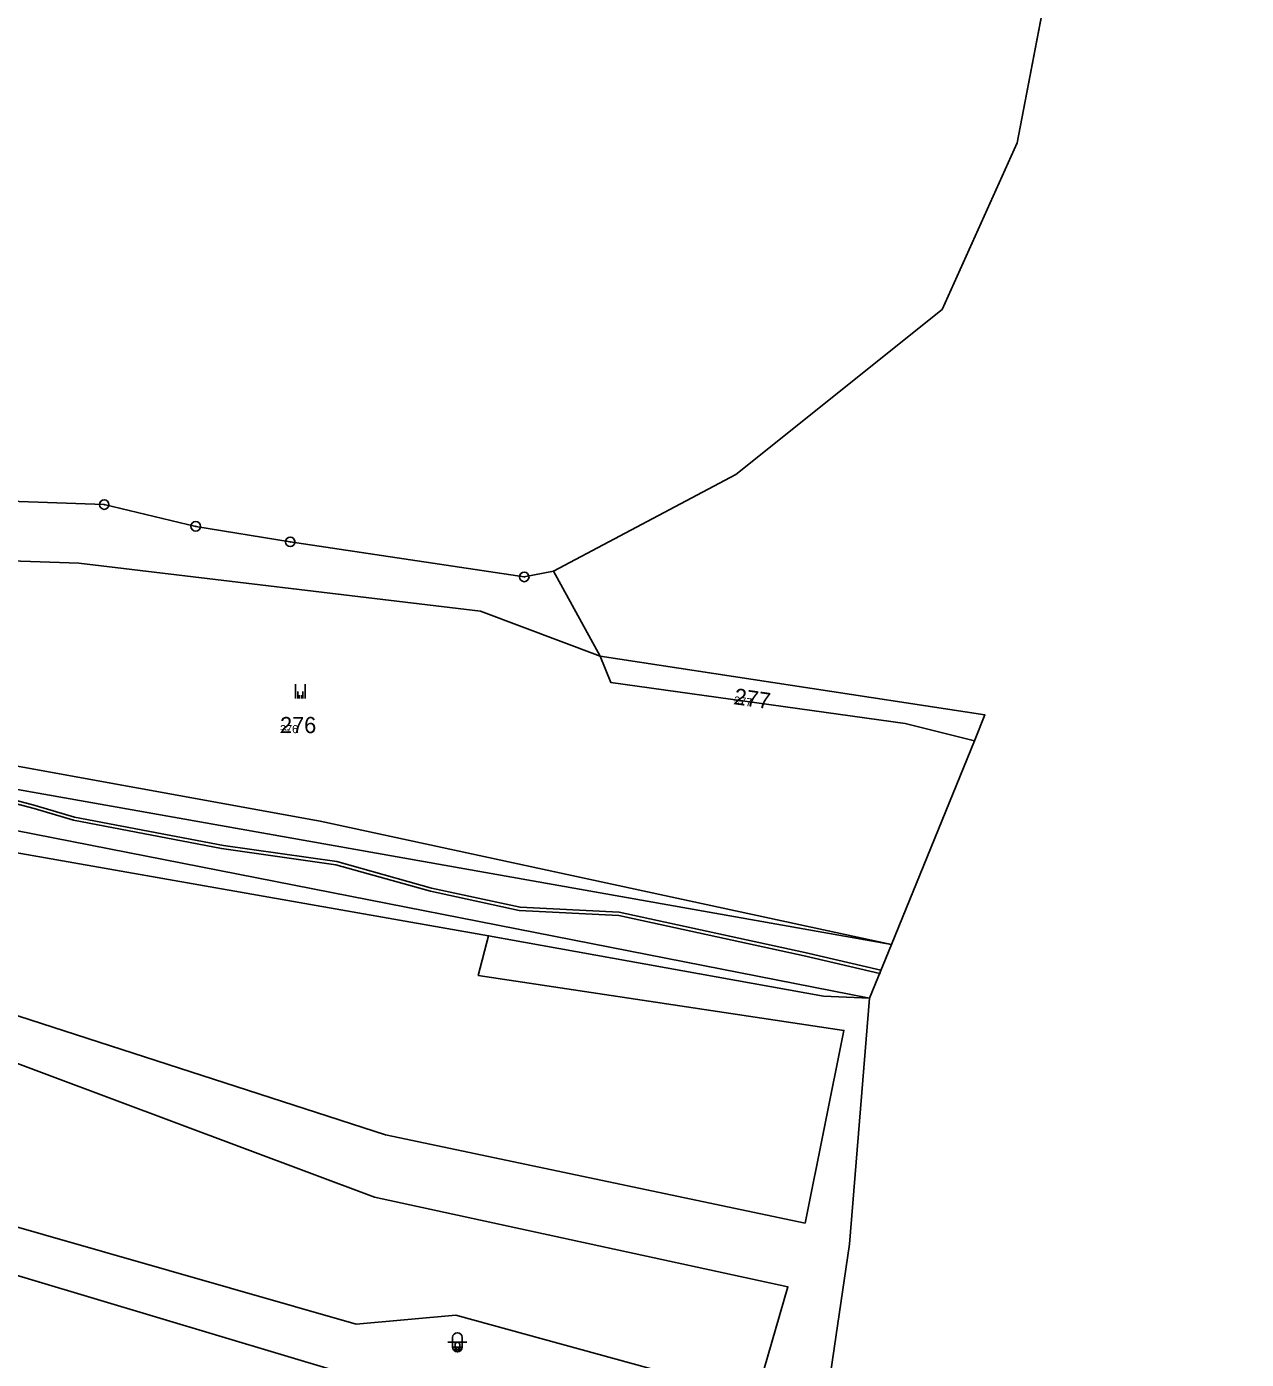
# Model space of a CAD drawing. Extents: x -759873 to -758487, y -975024 to -973516.
# Drawn here: x -758688 to -758560.1, y -974535.9 to -974396.2 of the extents above; entities that cross this region are included whole.
import ezdxf

# ---------------------------------------------------------------- set-up
doc = ezdxf.new("R2010")
doc.units = 0
for name, color, linetype in [('KAT_01_hranice KU', 7, 'Continuous'), ('KAT_02_hranice parcel', 7, 'Continuous'), ('KAT_03_1000_čísla parcelní', 7, 'Continuous'), ('KAT_03_250_čísla parcelní', 7, 'Continuous'), ('KAT_03_500_čísla parcelní', 7, 'Continuous'), ('KAT_04_vnitřní kresba', 7, 'Continuous'), ('KAT_05_1000_značky kultur', 7, 'Continuous'), ('KAT_05_250_značky kultur', 7, 'Continuous'), ('KAT_05_500_značky kultur', 7, 'Continuous'), ('KAT_10_věcná břemena', 7, 'Continuous'), ('KAT_11_značky bodu BP', 7, 'Continuous'), ('KAT_14_plocha_pozemek', 7, 'Continuous')]:
    doc.layers.add(name, color=color, linetype=linetype)

msp = doc.modelspace()

# ---------------------------------------------------------------- linework, layer by layer
at = {"layer": 'KAT_01_hranice KU'}
msp.add_lwpolyline([(-758607.97, -974566.39), (-758601.73, -974523.85), (-758599.61, -974498.06), (-758597.31, -974492.42), (-758588.63, -974471.08), (-758587.52, -974468.35), (-758627.86, -974462.19), (-758632.75, -974453.28), (-758613.64, -974443.17), (-758592.01, -974425.87), (-758584.15, -974408.39), (-758577.48, -974373.63), (-758560.12, -974371.49), (-758566.72, -974342.84), (-758577.45, -974305.32), (-758579.96, -974284.59)], dxfattribs=at)
at = {"layer": 'KAT_02_hranice parcel'}
for p, q in [((-758584.15, -974408.39), (-758577.48, -974373.63)), ((-758592.01, -974425.87), (-758584.15, -974408.39)), ((-758613.64, -974443.17), (-758592.01, -974425.87)), ((-758632.75, -974453.28), (-758613.64, -974443.17)), ((-758627.86, -974462.19), (-758632.75, -974453.28)), ((-758587.52, -974468.35), (-758627.86, -974462.19)), ((-758588.63, -974471.08), (-758587.52, -974468.35)), ((-758597.31, -974492.42), (-758588.63, -974471.08)), ((-758599.61, -974498.06), (-758597.31, -974492.42))]:
    msp.add_line(p, q, dxfattribs=at)
for points in [[(-758632.75, -974453.28), (-758635.81, -974453.89), (-758660.34, -974450.22), (-758670.25, -974448.59), (-758679.84, -974446.31), (-758718.48, -974444.93), (-758753.38, -974423.47), (-758781.23, -974399.3), (-758797.06, -974363.45), (-758834.16, -974346.1), (-758865.99, -974333.25), (-758907.24, -974318.32), (-758952.22, -974315.62)], [(-758718.12, -974451.24), (-758682.5, -974452.45), (-758640.39, -974457.49), (-758627.86, -974462.19)], [(-758588.63, -974471.08), (-758595.89, -974469.25), (-758626.75, -974464.95), (-758627.86, -974462.19)], [(-758597.31, -974492.42), (-758602.67, -974491.26), (-758657.21, -974479.48), (-758695.33, -974472.59), (-758723.99, -974463.52)], [(-758727.47, -974470.86), (-758699.13, -974481.04), (-758639.55, -974491.51)], [(-758639.55, -974491.51), (-758640.63, -974495.69), (-758602.31, -974501.43), (-758606.38, -974521.63), (-758650.34, -974512.39), (-758704.47, -974494.86), (-758706.61, -974498.3), (-758651.5, -974518.9), (-758608.18, -974528.3), (-758611.55, -974539.9), (-758642.99, -974531.28), (-758653.42, -974532.21), (-758712.61, -974515.26), (-758713.61, -974519.76), (-758648.23, -974539.32), (-758612.86, -974545.85), (-758615.06, -974562.12), (-758700.21, -974537.79), (-758703.41, -974545.99), (-758657.92, -974561.88), (-758653.86, -974564.39)], [(-758599.61, -974498.06), (-758604.44, -974497.84), (-758639.55, -974491.51)], [(-758607.97, -974566.39), (-758601.73, -974523.85), (-758599.61, -974498.06)]]:
    msp.add_lwpolyline(points, dxfattribs=at)
at = {"layer": 'KAT_04_vnitřní kresba'}
for p, q in [((-758696.4, -974474.85), (-758597.31, -974492.42)), ((-758697.6, -974478.8), (-758599.61, -974498.06))]:
    msp.add_line(p, q, dxfattribs=at)
at = {"layer": 'KAT_05_1000_značky kultur'}
for p, q in [((-758659.78, -974466.64), (-758659.78, -974465.14)), ((-758658.78, -974466.64), (-758658.78, -974465.14)), ((-758643.82, -974534.12), (-758641.82, -974534.12)), ((-758643.32, -974533.62), (-758643.32, -974534.62)), ((-758642.32, -974534.62), (-758642.32, -974533.62))]:
    msp.add_line(p, q, dxfattribs=at)
for centre, start, end in [((-758642.82, -974533.62), 0, 180), ((-758642.82, -974534.62), 180, 359.9879)]:
    msp.add_arc(centre, 0.5, start, end, dxfattribs=at)
at = {"layer": 'KAT_05_250_značky kultur'}
for p, q in [((-758659.4, -974466.64), (-758659.4, -974466.27)), ((-758659.15, -974466.64), (-758659.15, -974466.27)), ((-758643.07, -974534.87), (-758642.57, -974534.87)), ((-758642.95, -974534.75), (-758642.95, -974535)), ((-758642.69, -974535), (-758642.69, -974534.75))]:
    msp.add_line(p, q, dxfattribs=at)
for centre, start, end in [((-758642.82, -974534.75), 0, 180), ((-758642.82, -974535), 180, 359.9879)]:
    msp.add_arc(centre, 0.125, start, end, dxfattribs=at)
at = {"layer": 'KAT_05_500_značky kultur'}
for p, q in [((-758659.53, -974466.64), (-758659.53, -974465.89)), ((-758659.03, -974466.64), (-758659.03, -974465.89)), ((-758643.07, -974534.37), (-758643.07, -974534.87)), ((-758642.57, -974534.87), (-758642.57, -974534.37)), ((-758643.32, -974534.62), (-758642.32, -974534.62))]:
    msp.add_line(p, q, dxfattribs=at)
for centre, start, end in [((-758642.82, -974534.37), 0, 180), ((-758642.82, -974534.87), 180, 359.9879)]:
    msp.add_arc(centre, 0.25, start, end, dxfattribs=at)
at = {"layer": 'KAT_10_věcná břemena'}
msp.add_lwpolyline([(-758698.63, -974475.15), (-758687.19, -974478.18), (-758683.05, -974479.39), (-758667.55, -974482.35), (-758655.56, -974484.06), (-758645.65, -974486.85), (-758636.34, -974488.86), (-758625.91, -974489.38), (-758606.48, -974493.61), (-758598.55, -974495.46), (-758598.44, -974495.13), (-758606.4, -974493.27), (-758625.87, -974489.04), (-758636.24, -974488.52), (-758645.55, -974486.51), (-758655.46, -974483.72), (-758667.33, -974482.03), (-758682.95, -974479.06), (-758687.09, -974477.84), (-758698.47, -974474.83)], dxfattribs=at)
at = {"layer": 'KAT_11_značky bodu BP'}
for centre, radius in [((-758679.84, -974446.31), 0.5), ((-758679.84, -974446.31), 0.0303), ((-758670.25, -974448.59), 0.5), ((-758670.25, -974448.59), 0.0303), ((-758660.34, -974450.22), 0.5), ((-758660.34, -974450.22), 0.0303), ((-758635.81, -974453.89), 0.5), ((-758635.81, -974453.89), 0.0303)]:
    msp.add_circle(centre, radius, dxfattribs=at)
at = {"layer": 'KAT_14_plocha_pozemek'}
for points in [[(-758834.16, -974346.1), (-758797.06, -974363.45), (-758781.23, -974399.3), (-758753.38, -974423.47), (-758718.48, -974444.93), (-758679.84, -974446.31), (-758670.25, -974448.59), (-758660.34, -974450.22), (-758635.81, -974453.89), (-758632.75, -974453.28), (-758613.64, -974443.17), (-758592.01, -974425.87), (-758584.15, -974408.39), (-758577.48, -974373.63), (-758560.12, -974371.49), (-758566.72, -974342.84), (-758577.45, -974305.32), (-758579.96, -974284.59)], [(-758822.78, -974356.75), (-758805.35, -974369.54), (-758794.34, -974384.71), (-758781.96, -974405.06), (-758777.78, -974408.08), (-758761.72, -974419.22), (-758750.8, -974427.84), (-758717.38, -974449.33), (-758718.12, -974451.24), (-758682.5, -974452.45), (-758640.39, -974457.49), (-758627.86, -974462.19), (-758632.75, -974453.28), (-758635.81, -974453.89), (-758660.34, -974450.22), (-758670.25, -974448.59), (-758679.84, -974446.31), (-758718.48, -974444.93), (-758753.38, -974423.47), (-758781.23, -974399.3), (-758797.06, -974363.45), (-758834.16, -974346.1)], [(-758648.23, -974539.32), (-758713.61, -974519.76), (-758712.61, -974515.26), (-758653.42, -974532.21), (-758642.99, -974531.28), (-758611.55, -974539.9), (-758608.18, -974528.3), (-758651.5, -974518.9), (-758706.61, -974498.3), (-758704.47, -974494.86), (-758650.34, -974512.39), (-758606.38, -974521.63), (-758602.31, -974501.43), (-758640.63, -974495.69), (-758639.55, -974491.51), (-758699.13, -974481.04), (-758727.47, -974470.86), (-758750.74, -974459.82), (-758767.08, -974450.68), (-758783.72, -974438.99), (-758822.73, -974398.57)], [(-758607.97, -974566.39), (-758601.73, -974523.85), (-758599.61, -974498.06), (-758604.44, -974497.84), (-758639.55, -974491.51), (-758640.63, -974495.69), (-758602.31, -974501.43), (-758606.38, -974521.63), (-758650.34, -974512.39), (-758704.47, -974494.86), (-758706.61, -974498.3), (-758651.5, -974518.9), (-758608.18, -974528.3), (-758611.55, -974539.9), (-758642.99, -974531.28), (-758653.42, -974532.21), (-758712.61, -974515.26), (-758713.61, -974519.76), (-758648.23, -974539.32)]]:
    msp.add_lwpolyline(points, dxfattribs=at)
for points in [[(-758626.75, -974464.95), (-758627.86, -974462.19), (-758640.39, -974457.49), (-758682.5, -974452.45), (-758718.12, -974451.24), (-758723.99, -974463.52), (-758695.33, -974472.59), (-758657.21, -974479.48), (-758602.67, -974491.26), (-758597.31, -974492.42), (-758588.63, -974471.08), (-758595.89, -974469.25)], [(-758627.86, -974462.19), (-758626.75, -974464.95), (-758595.89, -974469.25), (-758588.63, -974471.08), (-758587.52, -974468.35)], [(-758597.31, -974492.42), (-758602.67, -974491.26), (-758657.21, -974479.48), (-758695.33, -974472.59), (-758723.99, -974463.52), (-758725.04, -974465.74), (-758727.11, -974470.1), (-758727.47, -974470.86), (-758699.13, -974481.04), (-758639.55, -974491.51), (-758604.44, -974497.84), (-758599.61, -974498.06)]]:
    msp.add_lwpolyline(points, close=True, dxfattribs=at)

# ---------------------------------------------------------------- texts
at = {"layer": 'KAT_03_1000_čísla parcelní'}
msp.add_text('277', height=1.7, rotation=352, dxfattribs=at).set_placement((-758613.89, -974467.23))
msp.add_text('276', height=1.7, dxfattribs=at).set_placement((-758661.41, -974470.27))
at = {"layer": 'KAT_03_250_čísla parcelní'}
msp.add_text('277', height=0.425, rotation=352, dxfattribs=at).set_placement((-758613.89, -974467.23))
msp.add_text('276', height=0.425, dxfattribs=at).set_placement((-758661.41, -974470.27))
at = {"layer": 'KAT_03_500_čísla parcelní'}
msp.add_text('277', height=0.85, rotation=352, dxfattribs=at).set_placement((-758613.89, -974467.23))
msp.add_text('276', height=0.85, dxfattribs=at).set_placement((-758661.41, -974470.27))

doc.saveas('drawing.dxf')
